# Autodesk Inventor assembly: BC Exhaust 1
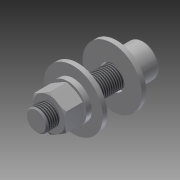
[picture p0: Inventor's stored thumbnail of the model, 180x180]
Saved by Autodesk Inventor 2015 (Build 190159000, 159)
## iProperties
Created: 2007-02
Part Number: BC Exhaust 1
Document SubType Name: Assembly
Designer: Autodesk, Inc.
Mass: 139.846 g
Surface Area: 109.169 cm^2
Volume: 17.7921 cm^3
Density: 7.86 g/cm^3
ClientObjectVersion: 1
Author: Autodesk, Inc.
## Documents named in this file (5)
- C:\Users\Public\Documents\Autodesk\Inventor 2015\Samples\Models\Assemblies\Blower\Blower\Design Accelerator\Bolted Connection Base Frame1.iam
- C:\Users\Public\Documents\Autodesk\Inventor 2015\Samples\Standard Parts\en-US\ANSI B18.22.1\ANSI B18.22.1 - 1_2 - wide - Type A.ipt
- C:\Users\Public\Documents\Autodesk\Inventor 2015\Samples\Standard Parts\en-US\ANSI B18.21.1\ANSI B18.21.1 - 0.5.ipt
- C:\Users\Public\Documents\Autodesk\Inventor 2015\Samples\Standard Parts\en-US\ANSI B18.3(13)\ANSI B18.3 - 1_2-20 UNF - 2(22).ipt
- C:\Users\Public\Documents\Autodesk\Inventor 2015\Samples\Standard Parts\en-US\ANSI B18.2.2(09)\ANSI B18.2.2 - 1_2 - 20(2).ipt
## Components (6 placed, 4 different names)
1. ANSI B18.22.1 - 1/2 - wide - Type A:1
2. ANSI B18.21.1 - 0.5:2
3. ANSI B18.3 - 1/2-20 UNF - 2:3
4. ANSI B18.22.1 - 1/2 - wide - Type A:4
5. ANSI B18.21.1 - 0.5:5
6. ANSI B18.2.2 - 1/2 - 20:6
